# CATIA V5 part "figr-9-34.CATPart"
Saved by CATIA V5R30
Part number: Part1
Bounding box of the stored display mesh (mm): x -250 to 0, y -60 to 60, z 0 to 100
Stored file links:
  D:\PROJECTS\CATIA V56R 2020\Resources\Parts File\c09_catia_v5_6r2020_prt\figr-9-34.CATPart
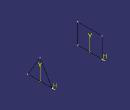
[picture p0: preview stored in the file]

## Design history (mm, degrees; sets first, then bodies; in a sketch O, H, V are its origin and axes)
Body1 (main body)
  Sketch1 on yz-plane, origin (0, 0, 0), H (0, 1, 0), V (0, 0, 1)
    point P1 (-60, 0)
    line L1 (-60, 0) -> (0, 100)
    point P2 (0, 100)
    line L2 (0, 100) -> (60, 0)
    point P3 (60, 0)
    line L3 (60, 0) -> (-60, 0)
    coincidence: P1 H, P2 V, P3 H
    horizontal: L3 H
    midpoint: O L3
  Sketch2, origin (-250, 0, 0), H (0, 1, 0), V (0, 0, 1)
    point P1 (-60, 0)
    line L1 (-60, 0) -> (60, 0)
    line L2 (60, 0) -> (60, 100)
    line L3 (60, 100) -> (-60, 100)
    line L4 (-60, 100) -> (-60, 0)
    coincidence: P1 H
    horizontal: L1 H, L3 H
    vertical: L2 V, L4 V
  Loft1: Sections (Sketch1; Sketch2), SectionCouplingPoints ({coupling CouplingPoints (vertex [element of Sketch1 | element of Sketch1]; vertex [element of Sketch2 | element of Sketch2])}; {coupling CouplingPoints (vertex [element of Sketch1 | element of Sketch1]; vertex [element of Sketch2 | element of Sketch2])}; {coupling CouplingPoints (vertex [element of Sketch1 | element of Sketch1]; vertex [element of Sketch2 | element of Sketch2])})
